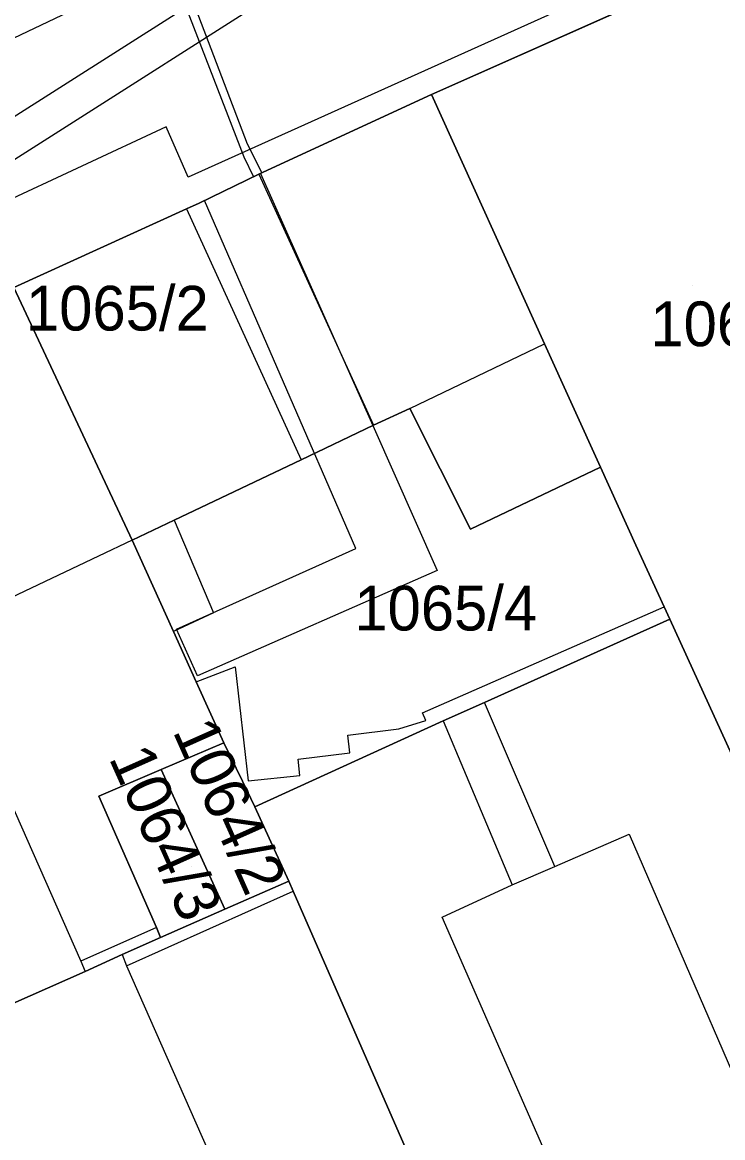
# Model space of a CAD drawing. Extents: x -263423 to -261326, y -1240067 to -1237864.
# Drawn here: x -262567.2 to -262535.87, y -1239776.12 to -1239726.22 of the extents above; entities that cross this region are included whole.
import ezdxf

# ---------------------------------------------------------------- set-up
doc = ezdxf.new("R2010")
doc.units = 0
for name, color, linetype in [('body_kn', 7, 'Continuous'), ('kladpar_druhypozemkov', 7, 'Continuous'), ('kladpar_hranice', 7, 'Continuous'), ('kladpar_parcelnecisla', 7, 'Continuous'), ('kladpar_plochy', 7, 'Continuous'), ('tarchy_linie', 7, 'Continuous'), ('zappar_hrandruhpozemk', 7, 'Continuous')]:
    doc.layers.add(name, color=color, linetype=linetype)

msp = doc.modelspace()

# ---------------------------------------------------------------- linework, layer by layer
at = {"layer": 'body_kn'}
for p, q in [((-262548.9, -1239729.45), (-262548.9, -1239729.45)), ((-262548.9, -1239729.45), (-262548.9, -1239729.45)), ((-262560.76, -1239730.9), (-262560.76, -1239730.9)), ((-262557.14, -1239731.66), (-262557.14, -1239731.66)), ((-262557.28, -1239732.24), (-262557.28, -1239732.24)), ((-262559.77, -1239733.15), (-262559.77, -1239733.15)), ((-262556.85, -1239733.13), (-262556.85, -1239733.13)), ((-262556.62, -1239733.02), (-262556.62, -1239733.02)), ((-262556.62, -1239733.02), (-262556.62, -1239733.02)), ((-262556.54, -1239732.98), (-262556.54, -1239732.98)), ((-262556.48, -1239732.95), (-262556.48, -1239732.95)), ((-262556.42, -1239732.92), (-262556.42, -1239732.92)), ((-262559.04, -1239734.19), (-262559.04, -1239734.19)), ((-262559.04, -1239734.19), (-262559.04, -1239734.19)), ((-262559.85, -1239734.56), (-262559.85, -1239734.56)), ((-262559.85, -1239734.56), (-262559.85, -1239734.56)), ((-262559.29, -1239734.31), (-262559.29, -1239734.31)), ((-262543.84, -1239740.6), (-262543.84, -1239740.6)), ((-262549.86, -1239743.5), (-262549.86, -1239743.5)), ((-262549.86, -1239743.5), (-262549.86, -1239743.5)), ((-262551.52, -1239744.26), (-262551.52, -1239744.26)), ((-262551.49, -1239744.25), (-262551.49, -1239744.25)), ((-262554.73, -1239745.79), (-262554.73, -1239745.79)), ((-262541.33, -1239746.12), (-262541.33, -1239746.12)), ((-262560.4, -1239748.49), (-262560.4, -1239748.49)), ((-262560.4, -1239748.49), (-262560.4, -1239748.49)), ((-262547.15, -1239748.9), (-262547.15, -1239748.9)), ((-262562.28, -1239749.39), (-262562.28, -1239749.39)), ((-262562.28, -1239749.39), (-262562.28, -1239749.39)), ((-262539.75, -1239749.61), (-262539.75, -1239749.61)), ((-262552.28, -1239749.76), (-262552.28, -1239749.76)), ((-262548.64, -1239750.74), (-262548.64, -1239750.74)), ((-262558.64, -1239752.64), (-262558.64, -1239752.64)), ((-262538.49, -1239752.37), (-262538.49, -1239752.37)), ((-262538.24, -1239752.93), (-262538.24, -1239752.93)), ((-262560.44, -1239753.47), (-262560.44, -1239753.47)), ((-262560.3, -1239753.37), (-262560.3, -1239753.37)), ((-262557.68, -1239755.05), (-262557.68, -1239755.05)), ((-262559.36, -1239755.46), (-262559.36, -1239755.46)), ((-262559.42, -1239755.72), (-262559.42, -1239755.72)), ((-262559.42, -1239755.72), (-262559.42, -1239755.72)), ((-262546.52, -1239756.65), (-262546.52, -1239756.65)), ((-262549.3, -1239757.11), (-262549.3, -1239757.11)), ((-262549.14, -1239757.46), (-262549.14, -1239757.46)), ((-262548.37, -1239757.47), (-262548.37, -1239757.47)), ((-262548.37, -1239757.47), (-262548.37, -1239757.47)), ((-262552.63, -1239758.12), (-262552.63, -1239758.12)), ((-262550.36, -1239757.83), (-262550.36, -1239757.83)), ((-262558.18, -1239758.45), (-262558.18, -1239758.45)), ((-262558.18, -1239758.45), (-262558.18, -1239758.45)), ((-262554.86, -1239759.18), (-262554.86, -1239759.18)), ((-262552.55, -1239758.91), (-262552.55, -1239758.91)), ((-262560.98, -1239759.65), (-262560.98, -1239759.65)), ((-262560.98, -1239759.65), (-262560.98, -1239759.65)), ((-262557.35, -1239760.17), (-262557.35, -1239760.17)), ((-262557.09, -1239760.16), (-262557.09, -1239760.16)), ((-262554.78, -1239759.92), (-262554.78, -1239759.92)), ((-262563.78, -1239760.84), (-262563.78, -1239760.84)), ((-262556.79, -1239761.32), (-262556.79, -1239761.32)), ((-262540.06, -1239762.54), (-262540.06, -1239762.54)), ((-262543.37, -1239763.99), (-262543.37, -1239763.99)), ((-262543.37, -1239763.99), (-262543.37, -1239763.99)), ((-262555.27, -1239764.64), (-262555.27, -1239764.64)), ((-262555.08, -1239765.09), (-262555.08, -1239765.09)), ((-262545.28, -1239764.81), (-262545.28, -1239764.81)), ((-262558.14, -1239765.9), (-262558.14, -1239765.9)), ((-262548.41, -1239766.26), (-262548.41, -1239766.26)), ((-262548.41, -1239766.26), (-262548.41, -1239766.26)), ((-262561.2, -1239766.72), (-262561.2, -1239766.72)), ((-262561.2, -1239766.72), (-262561.2, -1239766.72)), ((-262561.01, -1239767.16), (-262561.01, -1239767.16)), ((-262562.73, -1239767.92), (-262562.73, -1239767.92)), ((-262562.73, -1239767.92), (-262562.73, -1239767.92)), ((-262564.58, -1239768.23), (-262564.58, -1239768.23)), ((-262564.58, -1239768.23), (-262564.58, -1239768.23)), ((-262564.39, -1239768.68), (-262564.39, -1239768.68)), ((-262564.39, -1239768.68), (-262564.39, -1239768.68)), ((-262562.54, -1239768.43), (-262562.54, -1239768.43))]:
    msp.add_line(p, q, dxfattribs=at)
at = {"layer": 'kladpar_druhypozemkov'}
for p, q in [((-262561.65, -1239737.84), (-262561.65, -1239737.84)), ((-262537.22, -1239738.01), (-262537.22, -1239738.01)), ((-262547.44, -1239751.91), (-262547.44, -1239751.91)), ((-262556.42, -1239763.21), (-262556.42, -1239763.21)), ((-262559.62, -1239764.01), (-262559.62, -1239764.01))]:
    msp.add_line(p, q, dxfattribs=at)
at = {"layer": 'kladpar_hranice'}
for points in [[(-262451.68, -1239667.17), (-262451.23, -1239668.28), (-262460.7, -1239672.48), (-262459.45, -1239675.31), (-262450.08, -1239671.04), (-262449.88, -1239671.51), (-262445.64, -1239681.71), (-262444.85, -1239683.55), (-262470.85, -1239694.98), (-262473.53, -1239696.16), (-262490.19, -1239703.49), (-262516.65, -1239715.13), (-262520.79, -1239716.96), (-262535.01, -1239723.27), (-262548.9, -1239729.45), (-262556.42, -1239732.92), (-262556.62, -1239733.02), (-262559.29, -1239734.31), (-262559.85, -1239734.56), (-262567.58, -1239738.09)], [(-262521.13, -1239755.04), (-262528.27, -1239758.2), (-262529.21, -1239756.03), (-262535.46, -1239758.99), (-262538.24, -1239752.93), (-262538.49, -1239752.37), (-262539.75, -1239749.61), (-262541.33, -1239746.12), (-262543.84, -1239740.6), (-262548.9, -1239729.45), (-262535.01, -1239723.27), (-262521.13, -1239755.04)], [(-262548.9, -1239729.45), (-262543.84, -1239740.6), (-262541.33, -1239746.12), (-262547.15, -1239748.9), (-262549.86, -1239743.5), (-262551.49, -1239744.25), (-262554.73, -1239745.79), (-262560.4, -1239748.49), (-262562.28, -1239749.39), (-262567.58, -1239738.09), (-262559.85, -1239734.56), (-262559.29, -1239734.31), (-262556.62, -1239733.02), (-262556.42, -1239732.92), (-262548.9, -1239729.45)], [(-262567.58, -1239738.09), (-262562.28, -1239749.39), (-262560.44, -1239753.47), (-262559.42, -1239755.72), (-262558.18, -1239758.45), (-262560.98, -1239759.65), (-262563.78, -1239760.84), (-262561.2, -1239766.72), (-262561.01, -1239767.16), (-262562.73, -1239767.92), (-262564.39, -1239768.68), (-262575.93, -1239773.78), (-262587.66, -1239748.13), (-262587.79, -1239747.36), (-262587.47, -1239746.92), (-262567.58, -1239738.09)], [(-262562.28, -1239749.39), (-262560.4, -1239748.49), (-262554.73, -1239745.79), (-262551.49, -1239744.25), (-262549.86, -1239743.5), (-262547.15, -1239748.9), (-262541.33, -1239746.12), (-262539.75, -1239749.61), (-262538.49, -1239752.37), (-262538.24, -1239752.93), (-262546.52, -1239756.65), (-262548.37, -1239757.47), (-262556.79, -1239761.32), (-262557.35, -1239760.17), (-262558.18, -1239758.45), (-262559.42, -1239755.72), (-262560.44, -1239753.47), (-262562.28, -1239749.39)], [(-262548.37, -1239757.47), (-262546.52, -1239756.65), (-262538.24, -1239752.93), (-262535.46, -1239758.99), (-262534.51, -1239761.1), (-262521.46, -1239790.07), (-262540.33, -1239798.65), (-262546.38, -1239785), (-262555.08, -1239765.09), (-262555.27, -1239764.64), (-262556.79, -1239761.32), (-262548.37, -1239757.47)], [(-262558.18, -1239758.45), (-262557.35, -1239760.17), (-262556.79, -1239761.32), (-262555.27, -1239764.64), (-262558.14, -1239765.9), (-262560.98, -1239759.65), (-262558.18, -1239758.45)], [(-262560.98, -1239759.65), (-262558.14, -1239765.9), (-262561.01, -1239767.16), (-262561.2, -1239766.72), (-262563.78, -1239760.84), (-262560.98, -1239759.65)], [(-262564.39, -1239768.68), (-262562.73, -1239767.92), (-262561.01, -1239767.16), (-262558.14, -1239765.9), (-262555.27, -1239764.64), (-262555.08, -1239765.09), (-262546.38, -1239785), (-262540.33, -1239798.65), (-262560.41, -1239807.74), (-262575.93, -1239773.78), (-262564.39, -1239768.68)]]:
    msp.add_lwpolyline(points, dxfattribs=at)
at = {"layer": 'kladpar_plochy'}
for p, q in [((-262535.01, -1239723.27), (-262548.9, -1239729.45)), ((-262548.9, -1239729.45), (-262556.42, -1239732.92)), ((-262556.62, -1239733.02), (-262559.29, -1239734.31)), ((-262556.42, -1239732.92), (-262556.62, -1239733.02)), ((-262559.85, -1239734.56), (-262567.58, -1239738.09)), ((-262559.29, -1239734.31), (-262559.85, -1239734.56))]:
    msp.add_line(p, q, dxfattribs=at)
for points in [[(-262521.13, -1239755.04), (-262528.27, -1239758.2), (-262529.21, -1239756.03), (-262535.46, -1239758.99), (-262538.24, -1239752.93), (-262538.49, -1239752.37), (-262539.75, -1239749.61), (-262541.33, -1239746.12), (-262543.84, -1239740.6), (-262548.9, -1239729.45), (-262535.01, -1239723.27)], [(-262548.9, -1239729.45), (-262543.84, -1239740.6), (-262541.33, -1239746.12), (-262547.15, -1239748.9), (-262549.86, -1239743.5), (-262551.49, -1239744.25), (-262554.73, -1239745.79), (-262560.4, -1239748.49), (-262562.28, -1239749.39), (-262567.58, -1239738.09), (-262559.85, -1239734.56), (-262559.29, -1239734.31), (-262556.62, -1239733.02), (-262556.42, -1239732.92)], [(-262567.58, -1239738.09), (-262562.28, -1239749.39), (-262560.44, -1239753.47), (-262559.42, -1239755.72), (-262558.18, -1239758.45), (-262560.98, -1239759.65), (-262563.78, -1239760.84), (-262561.2, -1239766.72), (-262561.01, -1239767.16), (-262562.73, -1239767.92), (-262564.39, -1239768.68), (-262575.93, -1239773.78), (-262587.66, -1239748.13), (-262587.79, -1239747.36), (-262587.47, -1239746.92)], [(-262562.28, -1239749.39), (-262560.4, -1239748.49), (-262554.73, -1239745.79), (-262551.49, -1239744.25), (-262549.86, -1239743.5), (-262547.15, -1239748.9), (-262541.33, -1239746.12), (-262539.75, -1239749.61), (-262538.49, -1239752.37), (-262538.24, -1239752.93), (-262546.52, -1239756.65), (-262548.37, -1239757.47), (-262556.79, -1239761.32), (-262557.35, -1239760.17), (-262558.18, -1239758.45), (-262559.42, -1239755.72), (-262560.44, -1239753.47)], [(-262548.37, -1239757.47), (-262546.52, -1239756.65), (-262538.24, -1239752.93), (-262535.46, -1239758.99), (-262534.51, -1239761.1), (-262521.46, -1239790.07), (-262540.33, -1239798.65), (-262546.38, -1239785), (-262555.08, -1239765.09), (-262555.27, -1239764.64), (-262556.79, -1239761.32)], [(-262558.18, -1239758.45), (-262557.35, -1239760.17), (-262556.79, -1239761.32), (-262555.27, -1239764.64), (-262558.14, -1239765.9), (-262560.98, -1239759.65)], [(-262560.98, -1239759.65), (-262558.14, -1239765.9), (-262561.01, -1239767.16), (-262561.2, -1239766.72), (-262563.78, -1239760.84)], [(-262564.39, -1239768.68), (-262562.73, -1239767.92), (-262561.01, -1239767.16), (-262558.14, -1239765.9), (-262555.27, -1239764.64), (-262555.08, -1239765.09), (-262546.38, -1239785), (-262540.33, -1239798.65), (-262560.41, -1239807.74), (-262575.93, -1239773.78)]]:
    msp.add_lwpolyline(points, close=True, dxfattribs=at)
at = {"layer": 'tarchy_linie'}
for points in [[(-262563.05, -1239815.33), (-262589.16, -1239757.49), (-262590.95, -1239749.81), (-262588.59, -1239738.65), (-262582.68, -1239734.11), (-262511.84, -1239700.39), (-262476.21, -1239684.42), (-262449.67, -1239672.01)], [(-262569.51, -1239807.26), (-262582.81, -1239776.88), (-262594.07, -1239747.28), (-262557.61, -1239724.1), (-262509.31, -1239702.04), (-262475.06, -1239686.29), (-262448.71, -1239674.33)], [(-262508.62, -1239703.54), (-262556.82, -1239725.55), (-262588.51, -1239745.7), (-262589.37, -1239749.79), (-262587.69, -1239756.99), (-262562.28, -1239813.3), (-262498.48, -1239785.44)], [(-262560.71, -1239723.37), (-262557.28, -1239732.24), (-262556.85, -1239733.13)], [(-262559.68, -1239724.99), (-262557.14, -1239731.66), (-262556.48, -1239732.95)], [(-262559.04, -1239734.19), (-262556.62, -1239733.02), (-262556.54, -1239732.98), (-262551.52, -1239744.26), (-262548.64, -1239750.74), (-262559.36, -1239755.46), (-262560.3, -1239753.37), (-262552.28, -1239749.76), (-262559.04, -1239734.19)]]:
    msp.add_lwpolyline(points, dxfattribs=at)
at = {"layer": 'zappar_hrandruhpozemk'}
for p, q in [((-262445.64, -1239681.71), (-262559.77, -1239733.15)), ((-262560.76, -1239730.9), (-262568.33, -1239734.43)), ((-262559.77, -1239733.15), (-262560.76, -1239730.9)), ((-262556.62, -1239733.02), (-262551.49, -1239744.25)), ((-262559.85, -1239734.56), (-262554.73, -1239745.79)), ((-262549.86, -1239743.5), (-262543.84, -1239740.6)), ((-262562.28, -1239749.39), (-262571.07, -1239753.55)), ((-262549.3, -1239757.11), (-262538.49, -1239752.37)), ((-262571.07, -1239753.55), (-262564.58, -1239768.23)), ((-262559.42, -1239755.72), (-262557.68, -1239755.05)), ((-262557.68, -1239755.05), (-262557.09, -1239760.16)), ((-262543.37, -1239763.99), (-262546.52, -1239756.65)), ((-262548.37, -1239757.47), (-262545.28, -1239764.81)), ((-262552.63, -1239758.12), (-262550.36, -1239757.83)), ((-262562.54, -1239768.43), (-262555.08, -1239765.09)), ((-262541.03, -1239783.11), (-262548.41, -1239766.26)), ((-262561.2, -1239766.72), (-262564.58, -1239768.23)), ((-262562.73, -1239767.92), (-262562.54, -1239768.43)), ((-262564.58, -1239768.23), (-262564.39, -1239768.68)), ((-262562.54, -1239768.43), (-262554.53, -1239786.55))]:
    msp.add_line(p, q, dxfattribs=at)
for points in [[(-262560.4, -1239748.49), (-262558.64, -1239752.64), (-262560.44, -1239753.47)], [(-262550.36, -1239757.83), (-262549.14, -1239757.46), (-262549.3, -1239757.11)], [(-262557.09, -1239760.16), (-262554.78, -1239759.92), (-262554.86, -1239759.18), (-262552.55, -1239758.91), (-262552.63, -1239758.12)], [(-262548.41, -1239766.26), (-262545.28, -1239764.81), (-262543.37, -1239763.99), (-262540.06, -1239762.54), (-262532.74, -1239779.45)]]:
    msp.add_lwpolyline(points, dxfattribs=at)

# ---------------------------------------------------------------- texts
at = {"layer": 'kladpar_parcelnecisla'}
for s, p in [('1065/2', (-262567.034, -1239740.01)), ('1067', (-262539.105, -1239740.71)), ('1065/4', (-262552.347, -1239753.43))]:
    msp.add_text(s, height=2, dxfattribs=at).set_placement(p)
for s, p in [('1064/2', (-262560.488, -1239757.932)), ('1064/3', (-262563.344, -1239759.128))]:
    msp.add_text(s, height=2, rotation=294, dxfattribs=at).set_placement(p)

doc.saveas('drawing.dxf')
